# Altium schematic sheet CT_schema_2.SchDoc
size 357 x 214 mm
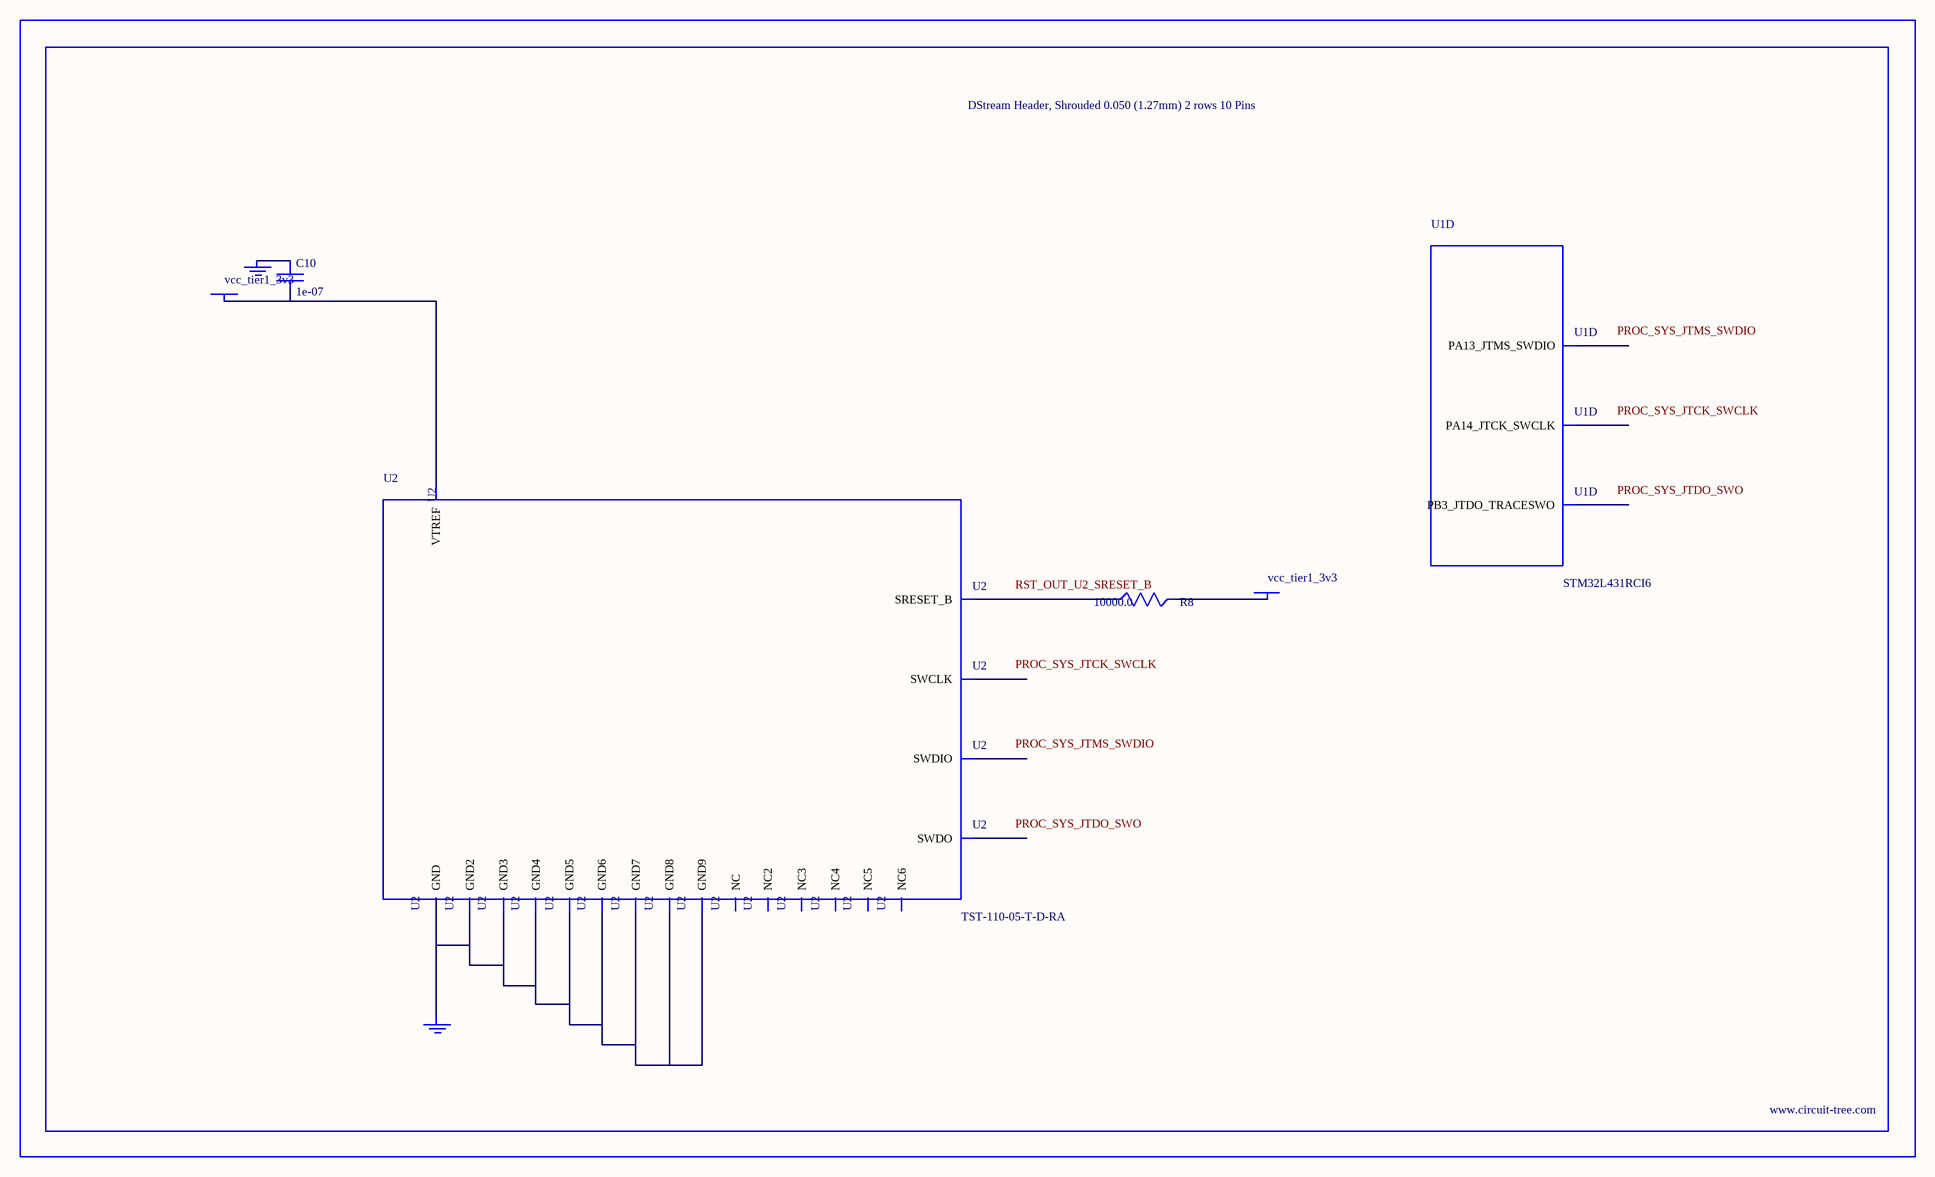
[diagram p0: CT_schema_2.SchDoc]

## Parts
BORDER1  (no value)
C10  1e-07  [C0402]
GND_INSTANCE_1_0  (no value)
GND_INSTANCE_1_1  (no value)
POWER_INSTANCE_1_0  vcc_tier1_3v3
POWER_INSTANCE_1_1  vcc_tier1_3v3
R8  10000.0  [R0603]
U1  STM32L431RCI6  [UFBGA64]  (part D of 6)
U2  TST-110-05-T-D-RA  [TST-110-05-T-D-RA]

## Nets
NetC10_1: C10.1 GND_INSTANCE_1_0.0(GND)
NetC10_2: C10.2 POWER_INSTANCE_1_0.0(PWR) U2.1(VTREF)
NetGND_INSTANCE_1_1_0: GND_INSTANCE_1_1.0(GND) U2.4(GND) U2.6(GND2) U2.8(GND3) U2.10(GND4) U2.12(GND5) U2.14(GND6) U2.16(GND7) U2.18(GND8) U2.20(GND9)
NetPOWER_INSTANCE_1_1_0: POWER_INSTANCE_1_1.0(PWR) R8.2
NetR8_1: R8.1 U2.15(SRESET_B)

Not connected (* = marked no-connect by the designer): U1 A5(PB3_JTDO_TRACESWO) A7(PA14_JTCK_SWCLK) A8(PA13_JTMS_SWDIO); U2 2(NC) 3(NC2) 5(NC3) 7(SWDIO) 9(SWCLK) 11(NC4) 13(SWDO) 17(NC5) 19(NC6)

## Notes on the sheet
- Labels drawn without touching a wire or pin: PROC_SYS_JTCK_SWCLK, PROC_SYS_JTDO_SWO, PROC_SYS_JTMS_SWDIO, RST_OUT_U2_SRESET_B

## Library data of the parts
BORDER1 = BORDER_PAGE1
C10 = C0402C104K3RACTU
GND_INSTANCE_1_0 GND_INSTANCE_1_1 = GND
POWER_INSTANCE_1_0 POWER_INSTANCE_1_1 = PWR
R8 = RC0603JR-0710KL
